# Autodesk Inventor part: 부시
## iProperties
Company: 한국ATC센터
Created: 2014-08
Part Number: 부시
Document SubType Name: Modeling
Designer: KYOUNG IL JANG
Density: 1 g/cm^3
Checked By: KYOUNG IL JANG
Material: 기본값
Mass: 6.39105 g
Surface Area: 30.183 cm^2
Volume: 6.39105 cm^3
Author: KYOUNG IL JANG
